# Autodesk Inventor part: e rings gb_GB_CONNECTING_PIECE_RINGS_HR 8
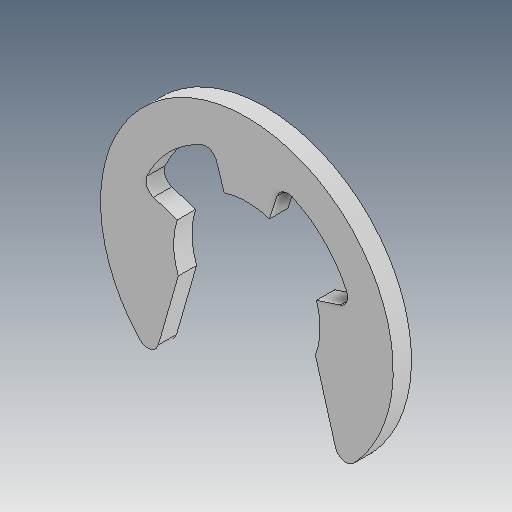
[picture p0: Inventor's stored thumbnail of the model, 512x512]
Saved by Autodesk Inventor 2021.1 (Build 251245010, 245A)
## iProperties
Created: 2019-04
Part Number: e rings gb_GB_CONNECTING_PIECE_RINGS_HR 8
Material: Ogólny
Document SubType Name: Modeling
Designer: user
Density: 1 g/cm^3
Appearance: Domyślna
Author: user
Revision Number: ÈÎºÎ
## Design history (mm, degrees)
feature "ÊäÈë1"
node "Bryła1"
